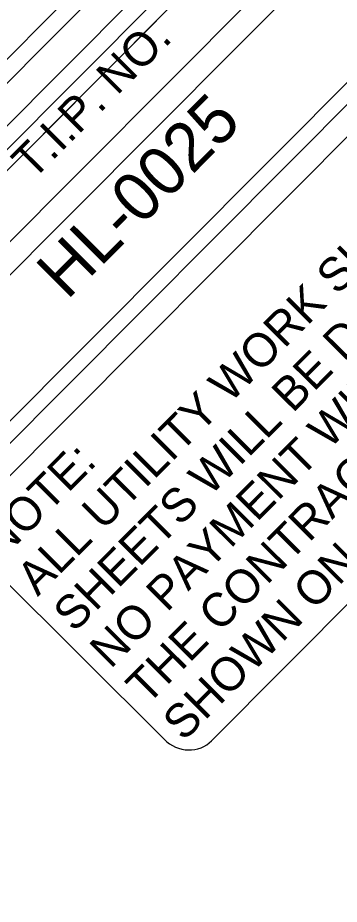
# Model space of a CAD drawing. Extents: x 1484850 to 1495577, y 495475 to 506245.
# Drawn here: x 1488133 to 1488420, y 500266 to 501057 of the extents above; entities that cross this region are included whole.
import ezdxf

# ---------------------------------------------------------------- set-up
doc = ezdxf.new("R2010")
doc.units = 0
for name, color, linetype in [('Cell Prop Down Guy _B', 7, 'Continuous'), ('Exist Utilities Power UG Cable SUE LOS C', 7, 'Continuous'), ('Prop Guy Wire', 7, 'Continuous'), ('Prop UG Pow Cables', 7, 'Continuous')]:
    doc.layers.add(name, color=color, linetype=linetype)

msp = doc.modelspace()

# ---------------------------------------------------------------- linework, layer by layer
at = {"layer": 'Cell Prop Down Guy _B'}
msp.add_line((1485019.38, 497803.89), (1488584.25, 501383.61), dxfattribs=at)
msp.add_lwpolyline([(1485019.38, 497803.89), (1488584.25, 501383.61), (1490922.52, 499055.04), (1487357.65, 495475.32)], close=True, dxfattribs=at)
at = {"layer": 'Exist Utilities Power UG Cable SUE LOS C'}
for p, q in [((1488480.65, 501319.74), (1487939.89, 500776.25)), ((1487941.57, 500757.11), (1488501.6, 501319.26)), ((1487983.69, 500714.74), (1488543.74, 501276.86)), ((1488063.91, 500635.07), (1488623.93, 501197.22)), ((1488082.63, 500633.83), (1488623.37, 501177.35)), ((1488637.93, 501163.12), (1488097.17, 500619.62)), ((1488305.67, 500411.72), (1488846.41, 500955.24)), ((1488098.74, 500577.15), (1488263.72, 500412.9))]:
    msp.add_line(p, q, dxfattribs=at)
msp.add_ellipse((1488284.13, 500433.42), major_axis=(21.78, -21.69), ratio=0.941469, start_param=4.712857, end_param=6.283654, dxfattribs=at)
at = {"layer": 'Prop Guy Wire'}
msp.add_lwpolyline([(1487337.48, 495550.45), (1490865.3, 499092.97), (1488622.45, 501326.52), (1485094.62, 497784)], close=True, dxfattribs=at)
at = {"layer": 'Prop UG Pow Cables'}
for points in [[(1488477.3, 501375.85), (1485344.2, 498229.75)], [(1488477.32, 501354.61), (1485471.34, 498336.11)]]:
    msp.add_lwpolyline(points, dxfattribs=at)

# ---------------------------------------------------------------- texts
at = {"layer": 'Exist Utilities Power UG Cable SUE LOS C'}
for s, height, p in [('ALL UTILITY WORK SHOWN ON THESE ', 30, (1488150.67, 500540.02)), ('T.I.P. NO.', 29.947, (1488146.28, 500911.38)), ('SHEETS WILL BE DONE BY OTHERS. ', 30, (1488183.22, 500507.63)), ('THE CONTRACTOR FOR UTILITY WORK ', 30, (1488248.34, 500442.85)), ('HL-0025', 43.39, (1488176.99, 500804.41)), ('NO PAYMENT WILL BE MADE TO ', 30, (1488215.78, 500475.24)), ('SHOWN ON THESE SHEETS.', 30, (1488280.9, 500410.46)), ('NOTE:', 30, (1488118.11, 500572.42))]:
    msp.add_text(s, height=height, rotation=45.14762, dxfattribs=at).set_placement(p)

doc.saveas('drawing.dxf')
